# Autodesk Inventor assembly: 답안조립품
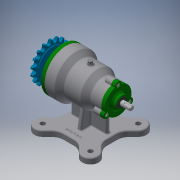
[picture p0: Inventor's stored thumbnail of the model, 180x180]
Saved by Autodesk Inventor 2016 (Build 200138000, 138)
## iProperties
Created: 2017-03
Part Number: 답안조립품
Material: 일반
Document SubType Name: Assembly
Designer: USER
Author: USER
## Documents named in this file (14)
- C:\Users\USER\Desktop\470308V1013\답안조립품.iam
- C:\Users\USER\Desktop\470308V1013\본체.ipt
- C:\Users\USER\Desktop\470308V1013\뒤커버.ipt
- C:\Users\USER\Desktop\470308V1013\베어링-6200.ipt
- C:\Users\USER\Desktop\470308V1013\베어링-6203.ipt
- C:\Users\USER\Desktop\470308V1013\볼트 M4 x 12.ipt
- C:\Users\USER\Desktop\470308V1013\볼트 M5 x 10.ipt
- 볼트 M5 x 10.ipt
- C:\Users\USER\Desktop\470308V1013\스프로킷.ipt
- C:\Users\USER\Desktop\470308V1013\앞커버.ipt
- C:\Users\USER\Desktop\470308V1013\오일 실 10 20 7.ipt
- C:\Users\USER\Desktop\470308V1013\오일 실 17 30 8.ipt
- C:\Users\USER\Desktop\470308V1013\축.ipt
- C:\Users\USER\Desktop\470308V1013\키5x5.ipt
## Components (9 placed, 1 different names)
1. ISO 4762 M4 x 12:1
2. ISO 4762 M4 x 12:2
3. ISO 4762 M4 x 12:3
4. ISO 4762 M4 x 12:4
5. ISO 4762 M4 x 12:5
6. ISO 4762 M4 x 12:6
7. ISO 4762 M4 x 12:7
8. ISO 4762 M4 x 12:8
9. ISO 4762 M4 x 12:9
